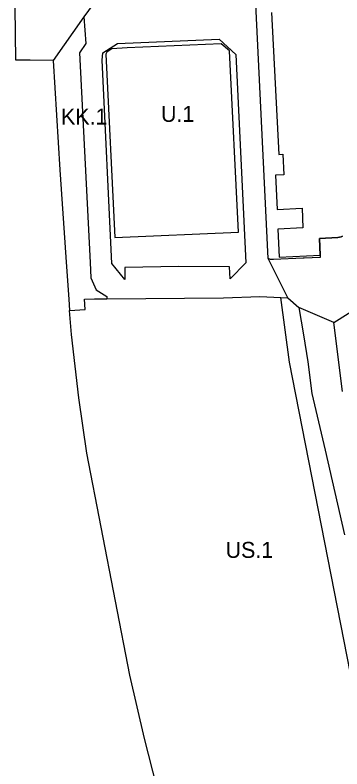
# Model space of a CAD drawing. Extents: x 7424052 to 7425705, y 5546602 to 5547569.
# Drawn here: x 7424667.4 to 7424769.6, y 5547200.9 to 5547436.7 of the extents above; entities that cross this region are included whole.
import ezdxf

# ---------------------------------------------------------------- set-up
doc = ezdxf.new("R2010")
doc.units = 0
for name, color, linetype in [('linie rozgraniczające', 7, 'Continuous'), ('nieprzekraczalne linie zabudowy', 7, 'Continuous'), ('obowiazujace linie zabudowy', 7, 'Continuous'), ('przeznaczenia terenów', 7, 'Continuous')]:
    doc.layers.add(name, color=color, linetype=linetype)

msp = doc.modelspace()

# ---------------------------------------------------------------- linework, layer by layer
at = {"layer": 'linie rozgraniczające'}
for p, q in [((7424746.58, 5547360.62), (7424742.39, 5547447.09)), ((7424695.29, 5547445.12), (7424688.94, 5547436.14)), ((7424667.64, 5547422.58), (7424667.44, 5547439.14)), ((7424688.94, 5547436.14), (7424679.35, 5547422.55)), ((7424688.94, 5547436.14), (7424689.58, 5547427.86)), ((7424689.58, 5547427.86), (7424687.55, 5547424.85)), ((7424694.91, 5547424.88), (7424699.44, 5547427.8)), ((7424699.44, 5547427.8), (7424731.24, 5547429.15)), ((7424731.24, 5547429.15), (7424736.47, 5547424.37)), ((7424687.55, 5547424.85), (7424690.91, 5547359.35)), ((7424694.69, 5547422.59), (7424694.91, 5547424.88)), ((7424736.47, 5547424.37), (7424739.61, 5547359.23)), ((7424679.35, 5547422.55), (7424681.44, 5547388.34)), ((7424697.74, 5547358.98), (7424694.69, 5547422.59)), ((7424681.44, 5547388.34), (7424683.52, 5547358)), ((7424768.35, 5547367.14), (7424762.66, 5547366.85)), ((7424762.66, 5547366.85), (7424762.86, 5547361.58)), ((7424769.45, 5547367.39), (7424768.35, 5547367.14)), ((7424769.87, 5547367.59), (7424769.45, 5547367.39)), ((7424752.75, 5547348.32), (7424746.58, 5547360.62)), ((7424747.33, 5547360.28), (7424746.58, 5547360.62)), ((7424748.23, 5547360.29), (7424747.33, 5547360.28)), ((7424757.51, 5547360.67), (7424748.23, 5547360.29)), ((7424757.87, 5547360.68), (7424757.51, 5547360.67)), ((7424762.86, 5547360.89), (7424757.87, 5547360.68)), ((7424762.86, 5547361.58), (7424762.86, 5547360.89)), ((7424683.52, 5547358), (7424683.52, 5547358)), ((7424683.52, 5547358), (7424684.21, 5547347.87)), ((7424690.91, 5547359.35), (7424691.16, 5547354.49)), ((7424701.79, 5547354.01), (7424697.74, 5547358.98)), ((7424718.67, 5547358.05), (7424701.77, 5547357.79)), ((7424701.77, 5547357.79), (7424701.79, 5547354.01)), ((7424734.51, 5547357.93), (7424718.67, 5547358.05)), ((7424734.71, 5547354.21), (7424734.51, 5547357.93)), ((7424739.61, 5547359.23), (7424734.71, 5547354.21)), ((7424691.16, 5547354.49), (7424692.83, 5547350.77)), ((7424692.83, 5547350.77), (7424696.15, 5547348.65)), ((7424684.21, 5547347.87), (7424684.49, 5547344.32)), ((7424689.16, 5547347.91), (7424692.27, 5547347.94)), ((7424689.33, 5547344.65), (7424689.16, 5547347.91)), ((7424692.27, 5547347.94), (7424696.14, 5547347.97)), ((7424696.15, 5547348.65), (7424696.14, 5547347.97)), ((7424696.14, 5547347.97), (7424732.58, 5547348.24)), ((7424732.58, 5547348.24), (7424743.96, 5547348.69)), ((7424743.96, 5547348.69), (7424752.75, 5547348.32)), ((7424752.75, 5547348.32), (7424756.21, 5547345.23)), ((7424767.07, 5547340.61), (7424756.21, 5547345.23)), ((7424756.21, 5547345.23), (7424757.61, 5547336.72)), ((7424767.07, 5547340.61), (7424776.17, 5547346.31)), ((7424684.49, 5547344.32), (7424689.33, 5547344.65)), ((7424685.08, 5547336.86), (7424684.49, 5547344.32)), ((7424769.83, 5547318.95), (7424767.07, 5547340.61)), ((7424687.39, 5547316.95), (7424685.08, 5547336.86)), ((7424757.61, 5547336.72), (7424759.01, 5547328.21)), ((7424759.01, 5547328.21), (7424760.21, 5547318.33)), ((7424689.86, 5547299.7), (7424687.39, 5547316.95)), ((7424760.21, 5547318.33), (7424764.44, 5547300.62)), ((7424764.44, 5547300.62), (7424770.4, 5547274.14)), ((7424703.31, 5547230.29), (7424689.86, 5547299.7)), ((7424707.94, 5547210.43), (7424703.31, 5547230.29)), ((7424716.56, 5547176.59), (7424707.94, 5547210.43))]:
    msp.add_line(p, q, dxfattribs=at)
msp.add_lwpolyline([(7424679.35, 5547422.55), (7424672.15, 5547422.57), (7424667.64, 5547422.58)], dxfattribs=at)
at = {"layer": 'nieprzekraczalne linie zabudowy'}
for p, q in [((7424697.69, 5547426.17), (7424696.1, 5547425.14)), ((7424702.46, 5547426.48), (7424697.69, 5547426.17)), ((7424731.92, 5547427.73), (7424702.46, 5547426.48)), ((7424734.47, 5547425.49), (7424731.92, 5547427.73)), ((7424737.3, 5547368.77), (7424734.47, 5547425.49)), ((7424696.1, 5547425.14), (7424695.78, 5547424.45)), ((7424695.78, 5547424.45), (7424698.64, 5547367.13)), ((7424698.64, 5547367.13), (7424737.3, 5547368.77)), ((7424753.24, 5547328.2), (7424750.56, 5547348.41)), ((7424774.34, 5547220.72), (7424753.24, 5547328.2))]:
    msp.add_line(p, q, dxfattribs=at)
at = {"layer": 'obowiazujace linie zabudowy'}
for points in [[(7424747.61, 5547437.48), (7424749.88, 5547393.13), (7424751.19, 5547393.19), (7424751.5, 5547386.74), (7424748.92, 5547386.62), (7424749.37, 5547375.93), (7424757.16, 5547376.3), (7424757.42, 5547370.14), (7424749.64, 5547369.77), (7424749.99, 5547360.99)], [(7424749.99, 5547360.99), (7424762.86, 5547361.58), (7424762.66, 5547366.85), (7424768.35, 5547367.14), (7424769.45, 5547367.39), (7424769.87, 5547367.59)]]:
    msp.add_lwpolyline(points, dxfattribs=at)

# ---------------------------------------------------------------- texts
at = {"layer": 'przeznaczenia terenów'}
for s, p in [('KK.1', (7424681.82, 5547402.48)), ('U.1', (7424713.08, 5547403.32)), ('US.1', (7424733.28, 5547266.94))]:
    msp.add_text(s, height=5, dxfattribs=at).set_placement(p)

doc.saveas('drawing.dxf')
